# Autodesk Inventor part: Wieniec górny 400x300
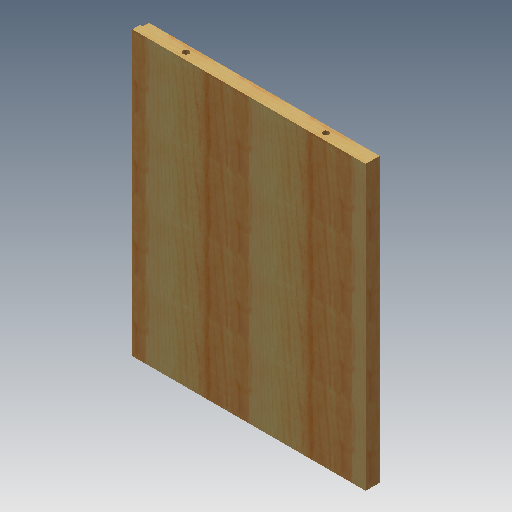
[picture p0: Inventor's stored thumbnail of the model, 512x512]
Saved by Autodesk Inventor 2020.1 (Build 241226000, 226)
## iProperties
Created: 2005-10
Part Number: Wieniec górny 400x300
Document SubType Name: Modeling
Designer: F.Stasiak
Density: 1 g/cm^3
Material: Ogólny
Appearance: Drewno (sosna)
Manager: www.cadconsulting.pl
Company: Fabian Stasiak CAD Consulting
Author: F.Stasiak
Subject: Zbiór ćwiczeń. Autodesk Inventor 2020. Kurs podstawowy
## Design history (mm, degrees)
sketch "Szkic1"
  geometry: L1 (-126.843, -31.953)-(173.157, -31.953); L2 (173.157, -31.953)-(173.157, -395.953); L3 (173.157, -395.953)-(-126.843, -395.953); L4 (-126.843, -395.953)-(-126.843, -31.953)
  constraints: 8 end point, 2 parallel, 1 horizontal, 1 perpendicular
  dimensions: "d0" = 300 distance of L1.start L1.end; "d1" = 364 distance of L1.end L2.end
extrude "Wyciągnięcie proste1" new body sketch "Szkic1" distance "d2" = 18; taper "d3" = 0 deg
sketch "Szkic2"
  geometry: L1 (300, 0)-(300, 18) reference; L2 (300, 18)-(0, 18) reference; L3 (0, 0)-(0, 18) reference; L4 (300, 0)-(0, 0) reference; L5 (0, 9)-(300, 9); 2 further points
  constraints: 2 end point, 2 midpoint, 2 point on line
  dimensions: "d4" = 180 distance of point (240, 9) point (60, 9); "d5" = 60 distance of L5.end point (240, 9)
hole "Otwór1" sketch "Szkic2" at (240, 9), (60, 9) diameter "d6" = 8; stored, may be unused: countersink angle "d10" = 90 deg, drill point angle "d12" = 118 deg; dims "d7" = 6, "d8" = 4, "d9" = 2, "d11" = 20
node "Płaszczyzna konstrukcyjna1"
mirror "Lustro1"
sketch "Szkic3"
  geometry: L1 (18, 0)-(18, 364) reference; L2 (0, 364)-(18, 364) reference; L3 (0, 0)-(0, 364) reference; L4 (0, 0)-(18, 0) reference; L5 (8, 364)-(0, 364); L6 (0, 364)-(0, 0); L7 (0, 0)-(8, 0); L8 (8, 0)-(8, 364)
  constraints: 8 end point, 3 collinear, 2 parallel, 1 horizontal, 1 perpendicular
  dimensions: "d19" = 8 distance between parallel lines of L8 L3
extrude "Wyciągnięcie proste2" cut sketch "Szkic3" distance "d20" = 3.5; taper "d21" = 0 deg
node "Bryła1"
node "Korpusy bryłowe"
node "Korpusy powierzchniowe"
node "Pętla rzutowana1"
node "Pętla rzutowana2"
